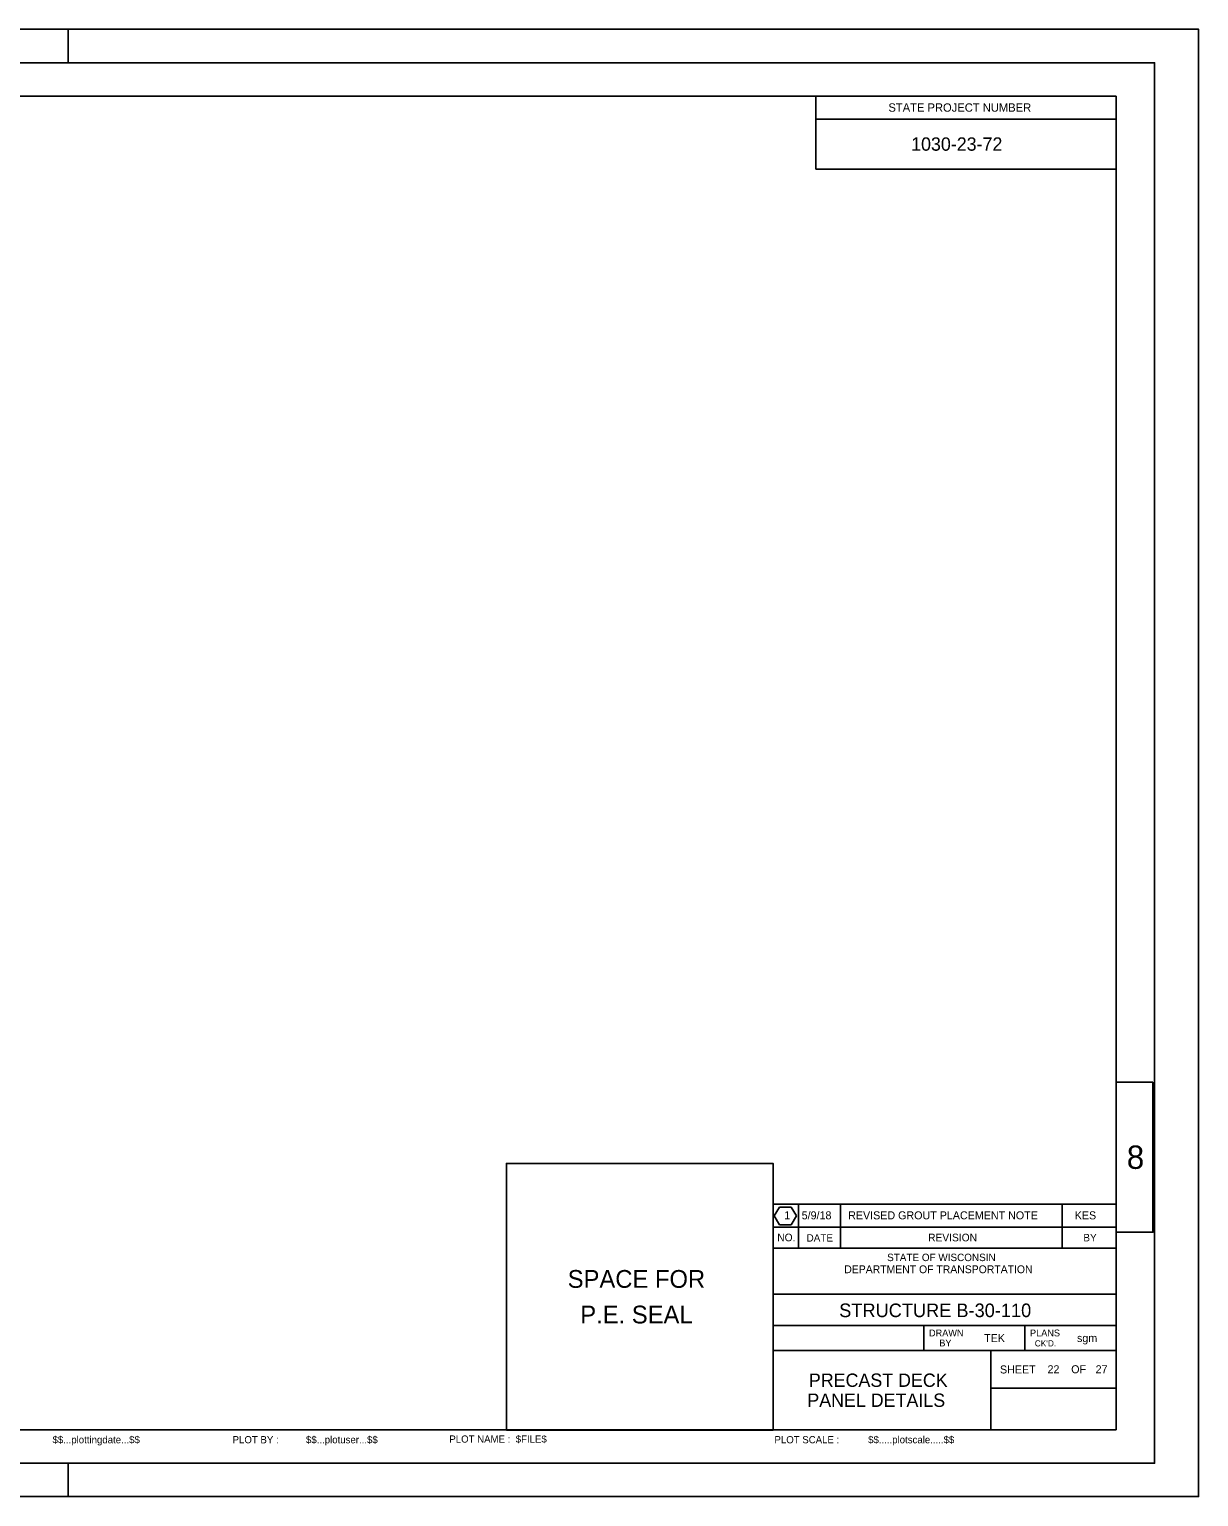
# Model space of a CAD drawing. Extents: x 0.2 to 45.6, y -46.3 to -16.9.
# Drawn here: x 22.17 to 45.55, y -46.26 to -16.93 of the extents above; entities that cross this region are included whole.
import ezdxf

# ---------------------------------------------------------------- set-up
doc = ezdxf.new("R2010")
doc.units = 0
for name, color, linetype in [('B_TEXT', 7, 'Continuous'), ('PLT_Sheet_Border', 7, 'Continuous'), ('PLT_Sheet_Info', 7, 'Continuous')]:
    doc.layers.add(name, color=color, linetype=linetype)

msp = doc.modelspace()

# ---------------------------------------------------------------- linework, layer by layer
at = {"layer": 'B_TEXT'}
for p, q in [((37.174, -40.476), (37.065, -40.651)), ((37.174, -40.476), (37.402, -40.476)), ((37.402, -40.476), (37.51, -40.651)), ((37.174, -40.827), (37.065, -40.651)), ((37.402, -40.827), (37.51, -40.651)), ((37.174, -40.827), (37.402, -40.827))]:
    msp.add_line(p, q, dxfattribs=at)
at = {"layer": 'PLT_Sheet_Border'}
for points in [[(0.218, -46.262), (45.551, -46.262), (45.551, -16.928), (0.218, -16.928)], [(0.538, -45.595), (44.671, -45.595), (44.671, -17.595), (0.538, -17.595)], [(31.711, -44.932), (37.044, -44.932), (37.044, -39.599), (31.711, -39.599)]]:
    msp.add_lwpolyline(points, close=True, dxfattribs=at)
at = {"layer": 'PLT_Sheet_Info'}
for p, q in [((22.284, -16.928), (23.618, -16.928)), ((22.951, -16.928), (22.951, -17.595)), ((44.218, -16.928), (45.551, -16.928)), ((45.551, -18.262), (45.551, -16.928)), ((1.905, -18.262), (43.905, -18.262)), ((37.897, -18.262), (37.897, -19.722)), ((43.905, -44.928), (43.905, -18.262)), ((37.897, -18.721), (43.905, -18.721)), ((37.897, -19.722), (43.905, -19.722)), ((37.044, -40.414), (43.909, -40.414)), ((37.044, -41.292), (37.044, -40.414)), ((37.551, -41.292), (37.551, -40.414)), ((38.388, -41.292), (38.388, -40.414)), ((42.822, -41.292), (42.822, -40.414)), ((37.044, -40.874), (43.909, -40.874)), ((37.044, -44.932), (37.044, -41.292)), ((37.044, -41.292), (43.909, -41.292)), ((37.044, -42.212), (43.909, -42.212)), ((37.044, -42.84), (43.909, -42.84)), ((40.057, -43.342), (40.057, -42.84)), ((42.074, -43.342), (42.074, -42.84)), ((37.044, -43.342), (43.909, -43.342)), ((41.395, -44.932), (41.395, -43.342)), ((41.396, -44.095), (43.905, -44.095)), ((1.905, -44.928), (43.905, -44.928)), ((45.551, -46.262), (45.551, -44.928)), ((22.951, -46.262), (22.951, -45.595)), ((22.284, -46.262), (23.618, -46.262)), ((44.218, -46.262), (45.551, -46.262))]:
    msp.add_line(p, q, dxfattribs=at)
msp.add_lwpolyline([(44.638, -37.976), (43.905, -37.976), (43.905, -40.976), (44.638, -40.976)], close=True, dxfattribs=at)

# ---------------------------------------------------------------- texts
at = {"layer": 'B_TEXT'}
for s, p in [('1', (37.266, -40.718)), ('5/9/18', (37.615, -40.718)), ('REVISED GROUT PLACEMENT NOTE', (38.544, -40.718)), ('KES', (43.074, -40.718))]:
    msp.add_text(s, height=0.16, dxfattribs=at).set_placement(p)
at = {"layer": 'PLT_Sheet_Border'}
for s, p in [('SPACE FOR', (32.937, -42.087)), ('P.E. SEAL', (33.188, -42.799))]:
    msp.add_text(s, height=0.3556, rotation=0, dxfattribs=at).set_placement(p)
at = {"layer": 'PLT_Sheet_Info'}
for s, height, p in [('STATE PROJECT NUMBER', 0.167, (39.349, -18.575)), ('1030-23-72', 0.2667, (39.803, -19.355)), ('8', 0.467, (44.115, -39.709)), ('NO.', 0.1525, (37.127, -41.156)), ('DATE', 0.1484, (37.712, -41.163)), ('REVISION', 0.1529, (40.143, -41.158)), ('BY', 0.1484, (43.247, -41.158)), ('DEPARTMENT OF TRANSPORTATION', 0.15587, (38.467, -41.794)), ('STATE OF WISCONSIN', 0.14828, (39.323, -41.553)), ('STRUCTURE B-30-110', 0.27189, (38.365, -42.673)), ('DRAWN', 0.1369, (40.16, -43.058)), ('TEK', 0.16, (41.262, -43.172)), ('PLANS', 0.137, (42.179, -43.058)), ('sgm', 0.16, (43.119, -43.171)), ('BY', 0.1366, (40.366, -43.258)), ("CK'D.", 0.1241, (42.275, -43.259)), ('SHEET', 0.16, (41.579, -43.799)), ('22', 0.16, (42.53, -43.795)), ('OF', 0.16, (43.003, -43.795)), ('27', 0.16, (43.491, -43.795)), ('PRECAST DECK', 0.26667, (37.759, -44.067)), ('PANEL DETAILS', 0.26667, (37.728, -44.467)), ('PLOT NAME :  $FILE$              ', 0.144, (30.571, -45.182)), ('PLOT SCALE : ', 0.144, (37.071, -45.195)), ('$$.....plotscale.....$$', 0.144, (38.943, -45.195))]:
    msp.add_text(s, height=height, dxfattribs=at).set_placement(p)
for s, p in [('$$...plottingdate...$$', (22.638, -45.195)), ('PLOT BY :', (26.238, -45.195)), ('$$...plotuser...$$', (27.705, -45.195))]:
    msp.add_text(s, height=0.144, rotation=360, dxfattribs=at).set_placement(p)

doc.saveas('drawing.dxf')
